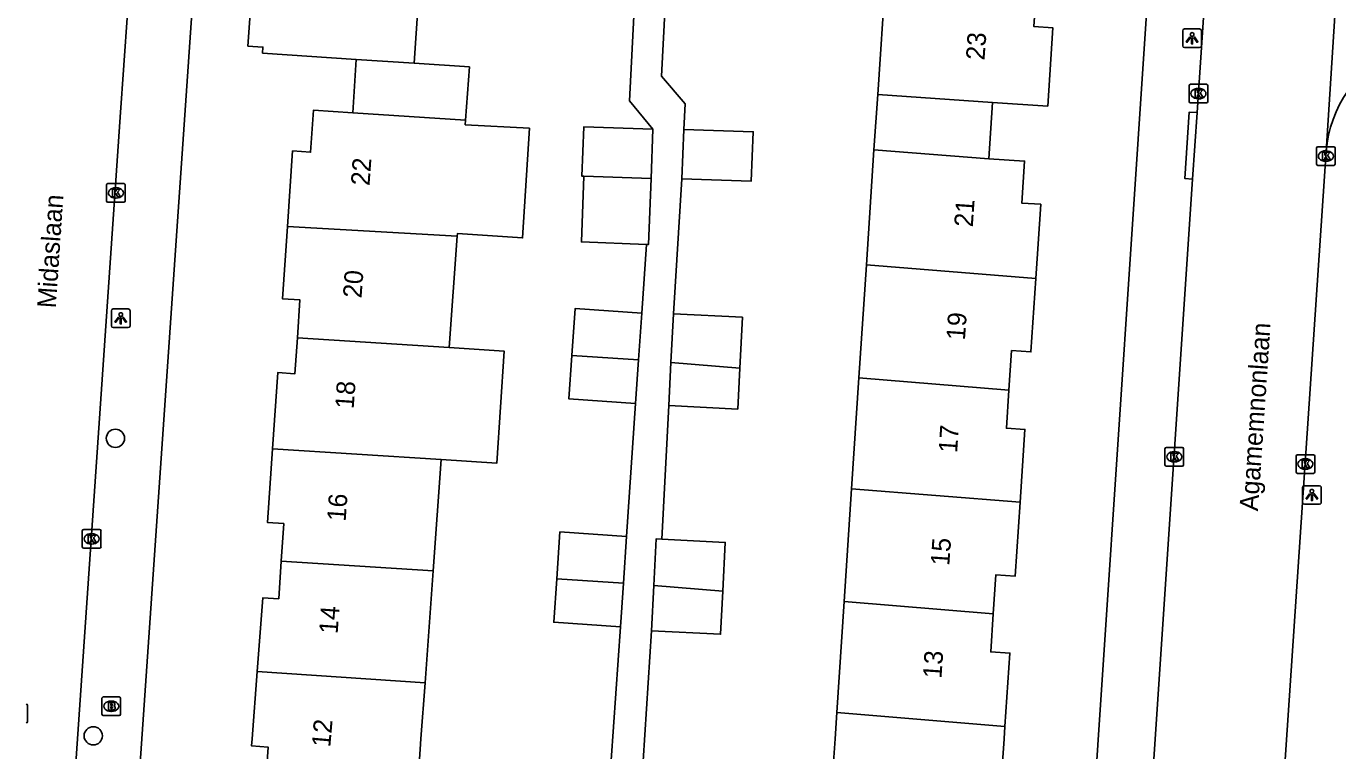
# Model space of a CAD drawing. Extents: x 161848 to 162726, y 385382 to 386521.
# Drawn here: x 162160.7 to 162231, y 385499.4 to 385538.2 of the extents above; entities that cross this region are included whole.
import ezdxf

# ---------------------------------------------------------------- set-up
doc = ezdxf.new("R2010")
doc.units = 0
for name, color, linetype in [('IMGEO_Boom', 7, 'Continuous'), ('IMGEO_Brandkraan', 7, 'Continuous'), ('IMGEO_Kolk', 7, 'Continuous'), ('IMGEO_Lichtpunt', 7, 'Continuous'), ('IMGEO_Openbare_ruimte_label', 7, 'Continuous'), ('IMGEO_Pand', 7, 'Continuous'), ('IMGEO_Pand_nummerreeks', 7, 'Continuous'), ('IMGEO_Rijbaan_lokaal_open', 7, 'Continuous'), ('IMGEO_Rioolput', 7, 'Continuous'), ('IMGEO_Voetpad_open', 7, 'Continuous')]:
    doc.layers.add(name, color=color, linetype=linetype)

msp = doc.modelspace()

# ---------------------------------------------------------------- linework, layer by layer
at = {"layer": 'IMGEO_Boom'}
for centre in [(162165.493, 385516.112), (162164.305, 385500.163)]:
    msp.add_circle(centre, 0.489, dxfattribs=at)
at = {"layer": 'IMGEO_Brandkraan'}
for p, q in [((162164.77, 385501.322), (162164.77, 385502.174)), ((162164.845, 385502.248), (162165.697, 385502.248)), ((162165.258, 385502.028), (162165.283, 385502.028)), ((162165.771, 385502.174), (162165.771, 385501.322)), ((162165.281, 385501.468), (162165.256, 385501.468)), ((162165.697, 385501.248), (162164.845, 385501.248))]:
    msp.add_line(p, q, dxfattribs=at)
for points in [[(162164.77, 385501.322), (162164.77, 385502.174)], [(162164.845, 385502.248), (162165.697, 385502.248)], [(162165.771, 385502.174), (162165.771, 385501.322)], [(162165.118, 385501.948), (162165.118, 385501.548), (162165.331, 385501.548)], [(162165.349, 385501.948), (162165.118, 385501.948)], [(162165.297, 385501.867), (162165.243, 385501.867), (162165.243, 385501.791)], [(162165.243, 385501.791), (162165.296, 385501.791)], [(162165.305, 385501.715), (162165.243, 385501.715), (162165.243, 385501.634)], [(162165.243, 385501.634), (162165.305, 385501.634)], [(162165.697, 385501.248), (162164.845, 385501.248)]]:
    msp.add_lwpolyline(points, dxfattribs=at)
for centre, radius, start, end in [((162164.847, 385502.172), 0.0765, 91.55205, 178.44795), ((162164.847, 385502.172), 0.0765, 91.55205, 178.44795), ((162165.695, 385502.172), 0.0765, 1.55205, 88.44795), ((162165.695, 385502.172), 0.0765, 1.55205, 88.44795), ((162164.847, 385501.324), 0.0765, 181.55205, 268.44795), ((162164.847, 385501.324), 0.0765, 181.55205, 268.44795), ((162165.298, 385501.829), 0.0379, 267.82845, 90.93552), ((162165.306, 385501.674), 0.0404, 269.87594, 90.50774), ((162165.337, 385501.799), 0.251, 268.66757, 293.53466), ((162165.353, 385501.803), 0.145, 59.4692, 91.53667), ((162165.378, 385501.85), 0.0922, 285.51372, 58.15012), ((162165.383, 385501.658), 0.105, 301.31148, 78.98903), ((162165.695, 385501.324), 0.0765, 271.55205, 358.44795), ((162165.695, 385501.324), 0.0765, 271.55205, 358.44795)]:
    msp.add_arc(centre, radius, start, end, dxfattribs=at)
for centre, major_axis, ratio, start_param, end_param in [((162165.257, 385501.748), (-0.387, 0.002), 0.722429, 4.712389, 7.853982), ((162165.282, 385501.748), (-0.39, 0.002), 0.717154, 1.570796, 4.712389)]:
    msp.add_ellipse(centre, major_axis=major_axis, ratio=ratio, start_param=start_param, end_param=end_param, dxfattribs=at)
at = {"layer": 'IMGEO_Kolk'}
for p, q in [((162223.096, 385535.09), (162223.948, 385535.09)), ((162223.021, 385534.164), (162223.021, 385535.016)), ((162223.509, 385534.87), (162223.534, 385534.87)), ((162224.022, 385535.016), (162224.022, 385534.164)), ((162223.948, 385534.09), (162223.096, 385534.09)), ((162223.532, 385534.31), (162223.507, 385534.31)), ((162229.846, 385530.818), (162229.846, 385531.67)), ((162229.921, 385531.744), (162230.773, 385531.744)), ((162230.334, 385531.524), (162230.359, 385531.524)), ((162230.847, 385531.67), (162230.847, 385530.818)), ((162230.357, 385530.964), (162230.332, 385530.964)), ((162230.773, 385530.744), (162229.921, 385530.744)), ((162165.018, 385528.84), (162165.018, 385529.692)), ((162165.093, 385529.766), (162165.945, 385529.766)), ((162165.506, 385529.546), (162165.531, 385529.546)), ((162166.019, 385529.692), (162166.019, 385528.84)), ((162165.945, 385528.766), (162165.093, 385528.766)), ((162165.529, 385528.986), (162165.504, 385528.986)), ((162221.727, 385514.698), (162221.727, 385515.55)), ((162221.802, 385515.624), (162222.654, 385515.624)), ((162222.215, 385515.404), (162222.24, 385515.404)), ((162222.728, 385515.55), (162222.728, 385514.698)), ((162222.238, 385514.844), (162222.213, 385514.844)), ((162228.752, 385514.308), (162228.752, 385515.16)), ((162228.827, 385515.234), (162229.679, 385515.234)), ((162229.24, 385515.014), (162229.265, 385515.014)), ((162229.753, 385515.16), (162229.753, 385514.308)), ((162222.654, 385514.624), (162221.802, 385514.624)), ((162229.679, 385514.234), (162228.827, 385514.234)), ((162229.263, 385514.454), (162229.238, 385514.454)), ((162163.719, 385510.296), (162163.719, 385511.148)), ((162163.794, 385511.222), (162164.646, 385511.222)), ((162164.72, 385511.148), (162164.72, 385510.296)), ((162164.23, 385510.442), (162164.205, 385510.442)), ((162164.207, 385511.002), (162164.232, 385511.002)), ((162164.646, 385510.222), (162163.794, 385510.222))]:
    msp.add_line(p, q, dxfattribs=at)
for points in [[(162223.096, 385535.09), (162223.948, 385535.09)], [(162223.021, 385534.164), (162223.021, 385535.016)], [(162223.342, 385534.79), (162223.465, 385534.79), (162223.465, 385534.639), (162223.595, 385534.79), (162223.759, 385534.79), (162223.613, 385534.639), (162223.766, 385534.39), (162223.614, 385534.39), (162223.529, 385534.554), (162223.465, 385534.487), (162223.465, 385534.39), (162223.342, 385534.39), (162223.342, 385534.79)], [(162224.022, 385535.016), (162224.022, 385534.164)], [(162223.948, 385534.09), (162223.096, 385534.09)], [(162229.846, 385530.818), (162229.846, 385531.67)], [(162229.921, 385531.744), (162230.773, 385531.744)], [(162230.847, 385531.67), (162230.847, 385530.818)], [(162230.167, 385531.444), (162230.29, 385531.444), (162230.29, 385531.293), (162230.42, 385531.444), (162230.584, 385531.444), (162230.438, 385531.293), (162230.591, 385531.044), (162230.439, 385531.044), (162230.354, 385531.208), (162230.29, 385531.141), (162230.29, 385531.044), (162230.167, 385531.044), (162230.167, 385531.444)], [(162230.773, 385530.744), (162229.921, 385530.744)], [(162165.018, 385528.84), (162165.018, 385529.692)], [(162165.093, 385529.766), (162165.945, 385529.766)], [(162165.339, 385529.466), (162165.462, 385529.466), (162165.462, 385529.315), (162165.592, 385529.466), (162165.756, 385529.466), (162165.61, 385529.315), (162165.763, 385529.066), (162165.611, 385529.066), (162165.526, 385529.23), (162165.462, 385529.163), (162165.462, 385529.066), (162165.339, 385529.066), (162165.339, 385529.466)], [(162166.019, 385529.692), (162166.019, 385528.84)], [(162165.945, 385528.766), (162165.093, 385528.766)], [(162221.727, 385514.698), (162221.727, 385515.55)], [(162221.802, 385515.624), (162222.654, 385515.624)], [(162222.728, 385515.55), (162222.728, 385514.698)], [(162222.048, 385515.324), (162222.171, 385515.324), (162222.171, 385515.173), (162222.301, 385515.324), (162222.465, 385515.324), (162222.319, 385515.173), (162222.472, 385514.924), (162222.32, 385514.924), (162222.235, 385515.088), (162222.171, 385515.021), (162222.171, 385514.924), (162222.048, 385514.924), (162222.048, 385515.324)], [(162228.752, 385514.308), (162228.752, 385515.16)], [(162228.827, 385515.234), (162229.679, 385515.234)], [(162229.073, 385514.934), (162229.196, 385514.934), (162229.196, 385514.783), (162229.326, 385514.934), (162229.49, 385514.934), (162229.344, 385514.783), (162229.497, 385514.534), (162229.345, 385514.534), (162229.26, 385514.698), (162229.196, 385514.631), (162229.196, 385514.534), (162229.073, 385514.534), (162229.073, 385514.934)], [(162229.753, 385515.16), (162229.753, 385514.308)], [(162222.654, 385514.624), (162221.802, 385514.624)], [(162229.679, 385514.234), (162228.827, 385514.234)], [(162163.719, 385510.296), (162163.719, 385511.148)], [(162163.794, 385511.222), (162164.646, 385511.222)], [(162164.72, 385511.148), (162164.72, 385510.296)], [(162164.04, 385510.922), (162164.163, 385510.922), (162164.163, 385510.771), (162164.293, 385510.922), (162164.457, 385510.922), (162164.311, 385510.771), (162164.464, 385510.522), (162164.312, 385510.522), (162164.227, 385510.686), (162164.163, 385510.619), (162164.163, 385510.522), (162164.04, 385510.522), (162164.04, 385510.922)], [(162164.646, 385510.222), (162163.794, 385510.222)]]:
    msp.add_lwpolyline(points, dxfattribs=at)
for centre, start, end in [((162223.098, 385535.014), 91.55205, 178.44795), ((162223.098, 385535.014), 91.55205, 178.44795), ((162223.946, 385535.014), 1.55205, 88.44795), ((162223.946, 385535.014), 1.55205, 88.44795), ((162223.098, 385534.166), 181.55205, 268.44795), ((162223.098, 385534.166), 181.55205, 268.44795), ((162223.946, 385534.166), 271.55205, 358.44795), ((162223.946, 385534.166), 271.55205, 358.44795), ((162229.923, 385531.668), 91.55205, 178.44795), ((162229.923, 385531.668), 91.55205, 178.44795), ((162230.771, 385531.668), 1.55205, 88.44795), ((162230.771, 385531.668), 1.55205, 88.44795), ((162229.923, 385530.82), 181.55205, 268.44795), ((162229.923, 385530.82), 181.55205, 268.44795), ((162230.771, 385530.82), 271.55205, 358.44795), ((162230.771, 385530.82), 271.55205, 358.44795), ((162165.095, 385529.69), 91.55205, 178.44795), ((162165.095, 385529.69), 91.55205, 178.44795), ((162165.943, 385529.69), 1.55205, 88.44795), ((162165.943, 385529.69), 1.55205, 88.44795), ((162165.095, 385528.842), 181.55205, 268.44795), ((162165.095, 385528.842), 181.55205, 268.44795), ((162165.943, 385528.842), 271.55205, 358.44795), ((162165.943, 385528.842), 271.55205, 358.44795), ((162221.804, 385515.548), 91.55205, 178.44795), ((162221.804, 385515.548), 91.55205, 178.44795), ((162222.652, 385515.548), 1.55205, 88.44795), ((162222.652, 385515.548), 1.55205, 88.44795), ((162221.804, 385514.7), 181.55205, 268.44795), ((162221.804, 385514.7), 181.55205, 268.44795), ((162222.652, 385514.7), 271.55205, 358.44795), ((162222.652, 385514.7), 271.55205, 358.44795), ((162228.829, 385515.158), 91.55205, 178.44795), ((162228.829, 385515.158), 91.55205, 178.44795), ((162229.677, 385515.158), 1.55205, 88.44795), ((162229.677, 385515.158), 1.55205, 88.44795), ((162228.829, 385514.31), 181.55205, 268.44795), ((162228.829, 385514.31), 181.55205, 268.44795), ((162229.677, 385514.31), 271.55205, 358.44795), ((162229.677, 385514.31), 271.55205, 358.44795), ((162163.796, 385511.146), 91.55205, 178.44795), ((162163.796, 385511.146), 91.55205, 178.44795), ((162164.644, 385511.146), 1.55205, 88.44795), ((162164.644, 385511.146), 1.55205, 88.44795), ((162163.796, 385510.298), 181.55205, 268.44795), ((162163.796, 385510.298), 181.55205, 268.44795), ((162164.644, 385510.298), 271.55205, 358.44795), ((162164.644, 385510.298), 271.55205, 358.44795)]:
    msp.add_arc(centre, 0.0765, start, end, dxfattribs=at)
for centre, major_axis, ratio, start_param, end_param in [((162223.508, 385534.59), (-0.387, 0.002), 0.722429, 4.712389, 7.853982), ((162223.533, 385534.59), (-0.39, 0.002), 0.717154, 1.570796, 4.712389), ((162230.333, 385531.244), (-0.387, 0.002), 0.722429, 4.712389, 7.853982), ((162230.358, 385531.244), (-0.39, 0.002), 0.717154, 1.570796, 4.712389), ((162165.505, 385529.266), (-0.387, 0.002), 0.722429, 4.712389, 7.853982), ((162165.53, 385529.266), (-0.39, 0.002), 0.717154, 1.570796, 4.712389), ((162222.214, 385515.124), (-0.387, 0.002), 0.722429, 4.712389, 7.853982), ((162222.239, 385515.124), (-0.39, 0.002), 0.717154, 1.570796, 4.712389), ((162229.239, 385514.734), (-0.387, 0.002), 0.722429, 4.712389, 7.853982), ((162229.264, 385514.734), (-0.39, 0.002), 0.717154, 1.570796, 4.712389), ((162164.206, 385510.722), (-0.387, 0.002), 0.722429, 4.712389, 7.853982), ((162164.231, 385510.722), (-0.39, 0.002), 0.717154, 1.570796, 4.712389)]:
    msp.add_ellipse(centre, major_axis=major_axis, ratio=ratio, start_param=start_param, end_param=end_param, dxfattribs=at)
at = {"layer": 'IMGEO_Lichtpunt'}
for p, q in [((162222.68, 385537.963), (162222.68, 385537.156)), ((162222.68, 385537.963), (162222.68, 385537.156)), ((162223.582, 385538.058), (162222.774, 385538.058)), ((162223.582, 385538.058), (162222.774, 385538.058)), ((162223.676, 385537.156), (162223.676, 385537.963)), ((162223.676, 385537.156), (162223.676, 385537.963)), ((162222.774, 385537.062), (162223.582, 385537.062)), ((162222.774, 385537.062), (162223.582, 385537.062)), ((162165.28, 385522.95), (162165.28, 385522.143)), ((162165.28, 385522.95), (162165.28, 385522.143)), ((162166.182, 385523.045), (162165.374, 385523.045)), ((162166.182, 385523.045), (162165.374, 385523.045)), ((162166.276, 385522.143), (162166.276, 385522.95)), ((162166.276, 385522.143), (162166.276, 385522.95)), ((162165.374, 385522.049), (162166.182, 385522.049)), ((162165.374, 385522.049), (162166.182, 385522.049)), ((162229.102, 385513.476), (162229.102, 385512.669)), ((162229.102, 385513.476), (162229.102, 385512.669)), ((162230.004, 385513.571), (162229.196, 385513.571)), ((162230.004, 385513.571), (162229.196, 385513.571)), ((162230.098, 385512.669), (162230.098, 385513.476)), ((162230.098, 385512.669), (162230.098, 385513.476)), ((162229.196, 385512.575), (162230.004, 385512.575)), ((162229.196, 385512.575), (162230.004, 385512.575))]:
    msp.add_line(p, q, dxfattribs=at)
for points in [[(162223.054, 385537.627), (162223.093, 385537.599), (162222.905, 385537.337), (162222.867, 385537.364), (162223.054, 385537.627)], [(162223.156, 385537.579), (162223.203, 385537.579), (162223.203, 385537.257), (162223.156, 385537.257), (162223.156, 385537.579)], [(162223.266, 385537.599), (162223.304, 385537.626), (162223.491, 385537.364), (162223.452, 385537.336), (162223.266, 385537.599)], [(162165.654, 385522.614), (162165.693, 385522.586), (162165.505, 385522.324), (162165.467, 385522.351), (162165.654, 385522.614)], [(162165.756, 385522.566), (162165.803, 385522.566), (162165.803, 385522.244), (162165.756, 385522.244), (162165.756, 385522.566)], [(162165.866, 385522.586), (162165.904, 385522.613), (162166.091, 385522.351), (162166.052, 385522.323), (162165.866, 385522.586)], [(162229.476, 385513.14), (162229.515, 385513.112), (162229.327, 385512.85), (162229.289, 385512.877), (162229.476, 385513.14)], [(162229.578, 385513.092), (162229.625, 385513.092), (162229.625, 385512.77), (162229.578, 385512.77), (162229.578, 385513.092)], [(162229.688, 385513.112), (162229.726, 385513.139), (162229.913, 385512.877), (162229.874, 385512.849), (162229.688, 385513.112)]]:
    msp.add_lwpolyline(points, dxfattribs=at)
for centre in [(162223.179, 385537.761), (162165.779, 385522.748), (162229.601, 385513.274)]:
    msp.add_circle(centre, 0.0994, dxfattribs=at)
for centre, start, end in [((162222.774, 385537.963), 90, 180), ((162222.774, 385537.963), 90, 180), ((162223.582, 385537.963), 0, 90), ((162223.582, 385537.963), 0, 90), ((162222.774, 385537.156), 180, 270), ((162222.774, 385537.156), 180, 270), ((162223.582, 385537.156), 270, 0), ((162223.582, 385537.156), 270, 360), ((162165.374, 385522.95), 90, 180), ((162165.374, 385522.95), 90, 180), ((162166.182, 385522.95), 0, 90), ((162166.182, 385522.95), 0, 90), ((162165.374, 385522.143), 180, 270), ((162165.374, 385522.143), 180, 270), ((162166.182, 385522.143), 270, 0), ((162166.182, 385522.143), 270, 360), ((162229.196, 385513.476), 90, 180), ((162229.196, 385513.476), 90, 180), ((162230.004, 385513.476), 0, 90), ((162230.004, 385513.476), 0, 90), ((162229.196, 385512.669), 180, 270), ((162229.196, 385512.669), 180, 270), ((162230.004, 385512.669), 270, 0), ((162230.004, 385512.669), 270, 360)]:
    msp.add_arc(centre, 0.0946, start, end, dxfattribs=at)
at = {"layer": 'IMGEO_Pand'}
for points in [[(162178.4, 385536.42), (162173.375, 385536.763), (162173.397, 385537.084), (162172.594, 385537.139), (162172.849, 385540.88), (162173.652, 385540.825), (162173.793, 385542.892)], [(162181.916, 385542.371), (162181.497, 385536.226)], [(162206.335, 385534.539), (162206.748, 385540.784)], [(162214.845, 385540.226), (162214.709, 385538.18), (162215.727, 385538.112), (162215.45, 385533.918), (162212.489, 385534.113)], [(162178.206, 385533.562), (162178.4, 385536.42)], [(162178.4, 385536.42), (162181.497, 385536.226)], [(162181.497, 385536.226), (162184.457, 385536.024), (162184.251, 385533.167)], [(162206.135, 385531.571), (162206.335, 385534.539)], [(162206.335, 385534.539), (162212.489, 385534.113)], [(162178.206, 385533.562), (162176.107, 385533.705), (162175.953, 385531.449), (162174.983, 385531.515), (162174.707, 385527.47)], [(162212.489, 385534.113), (162212.29, 385531.1)], [(162184.251, 385533.167), (162178.206, 385533.562)], [(162184.251, 385533.167), (162184.233, 385532.921), (162187.677, 385532.734), (162187.305, 385526.856), (162183.813, 385527.085), (162183.804, 385526.953)], [(162194.296, 385532.69), (162190.584, 385532.808), (162190.48, 385530.166), (162190.597, 385530.162)], [(162194.191, 385530.047), (162194.296, 385532.69)], [(162195.953, 385532.661), (162199.664, 385532.543), (162199.559, 385529.9), (162195.848, 385530.019)], [(162195.848, 385530.019), (162195.953, 385532.661)], [(162205.733, 385525.42), (162206.135, 385531.571)], [(162212.29, 385531.1), (162206.135, 385531.571)], [(162212.29, 385531.1), (162214.201, 385530.974), (162214.053, 385528.726), (162215.07, 385528.658), (162214.808, 385524.684)], [(162190.597, 385530.162), (162190.457, 385526.639), (162193.947, 385526.501)], [(162194.191, 385530.047), (162190.597, 385530.162)], [(162193.947, 385526.501), (162194.05, 385526.497), (162194.191, 385530.047)], [(162174.707, 385527.47), (162174.443, 385523.592), (162175.382, 385523.528), (162175.244, 385521.495)], [(162183.804, 385526.953), (162174.707, 385527.47)], [(162183.374, 385520.975), (162183.804, 385526.953)], [(162205.332, 385519.35), (162205.733, 385525.42)], [(162214.808, 385524.684), (162205.733, 385525.42)], [(162214.808, 385524.684), (162214.548, 385520.744), (162213.506, 385520.813), (162213.365, 385518.685)], [(162189.952, 385520.554), (162190.122, 385523.064), (162193.693, 385522.822)], [(162193.693, 385522.822), (162193.524, 385520.326)], [(162195.258, 385520.184), (162195.391, 385522.792)], [(162195.391, 385522.792), (162199.085, 385522.603), (162198.946, 385519.879)], [(162175.244, 385521.495), (162175.113, 385519.575), (162174.186, 385519.638), (162173.907, 385515.544)], [(162183.374, 385520.975), (162175.244, 385521.495)], [(162182.943, 385514.976), (162185.935, 385514.788), (162186.318, 385520.787), (162183.374, 385520.975)], [(162193.366, 385517.98), (162189.795, 385518.222), (162189.952, 385520.554)], [(162189.952, 385520.554), (162193.524, 385520.326)], [(162193.524, 385520.326), (162193.366, 385517.98)], [(162195.14, 385517.864), (162195.258, 385520.184)], [(162198.946, 385519.879), (162198.834, 385517.675), (162195.14, 385517.864)], [(162195.258, 385520.184), (162198.946, 385519.879)], [(162204.939, 385513.397), (162205.332, 385519.35)], [(162205.332, 385519.35), (162213.365, 385518.685)], [(162213.365, 385518.685), (162213.231, 385516.652), (162214.221, 385516.586), (162213.963, 385512.681)], [(162173.907, 385515.544), (162173.638, 385511.602), (162174.516, 385511.542), (162174.379, 385509.525)], [(162173.907, 385515.544), (162182.943, 385514.976)], [(162182.513, 385509.005), (162182.943, 385514.976)], [(162204.541, 385507.369), (162204.939, 385513.397)], [(162204.939, 385513.397), (162213.963, 385512.681)], [(162213.963, 385512.681), (162213.702, 385508.728), (162212.667, 385508.797), (162212.529, 385506.701)], [(162189.136, 385508.582), (162189.305, 385511.094), (162192.876, 385510.852)], [(162192.876, 385510.852), (162192.708, 385508.353)], [(162194.344, 385508.222), (162194.471, 385510.724), (162194.774, 385510.709)], [(162194.774, 385510.709), (162198.166, 385510.535), (162198.032, 385507.913)], [(162174.379, 385509.525), (162174.242, 385507.508), (162173.396, 385507.566), (162173.095, 385503.617)], [(162182.513, 385509.005), (162174.379, 385509.525)], [(162182.081, 385503.007), (162182.513, 385509.005)], [(162192.549, 385506.01), (162188.978, 385506.252), (162189.136, 385508.582)], [(162192.708, 385508.353), (162189.136, 385508.582)], [(162192.708, 385508.353), (162192.549, 385506.01)], [(162194.22, 385505.796), (162194.344, 385508.222)], [(162198.032, 385507.913), (162197.914, 385505.607), (162194.22, 385505.796)], [(162194.344, 385508.222), (162198.032, 385507.913)], [(162204.148, 385501.418), (162204.541, 385507.369)], [(162204.541, 385507.369), (162212.529, 385506.701)], [(162212.529, 385506.701), (162212.394, 385504.664), (162213.416, 385504.596), (162213.152, 385500.665)], [(162173.095, 385503.617), (162172.819, 385500), (162172.79, 385499.62), (162173.673, 385499.559), (162173.532, 385497.525)], [(162182.081, 385503.007), (162173.095, 385503.617)], [(162181.665, 385496.979), (162181.865, 385500), (162182.081, 385503.007)], [(162203.737, 385495.507), (162204.054, 385500), (162204.148, 385501.418)], [(162213.152, 385500.665), (162204.148, 385501.418)], [(162213.152, 385500.665), (162213.107, 385500), (162212.888, 385496.736), (162211.828, 385496.796), (162211.725, 385494.976)]]:
    msp.add_lwpolyline(points, dxfattribs=at)
at = {"layer": 'IMGEO_Rijbaan_lokaal_open'}
for points in [[(162168.482, 385573.131), (162166.136, 385538.907), (162165.753, 385533.321), (162163.468, 385500), (162161.151, 385466.324)], [(162223.444, 385533.57), (162225.631, 385566.308)], [(162230.36, 385531.483), (162231.543, 385549.956)], [(162223.444, 385533.57), (162223.206, 385530.013)], [(162230.36, 385531.483), (162221.906, 385405.85), (162221.191, 385395.939)], [(162218.979, 385466.744), (162223.206, 385530.013)]]:
    msp.add_lwpolyline(points, dxfattribs=at)
msp.add_arc((162236.918, 385530.965), 6.578, 114.27767, 175.48037, dxfattribs=at)
at = {"layer": 'IMGEO_Rioolput'}
msp.add_line((162160.788, 385501.783), (162160.788, 385500.931), dxfattribs=at)
msp.add_lwpolyline([(162160.788, 385501.783), (162160.788, 385500.931)], dxfattribs=at)
for centre, start, end in [((162160.712, 385501.781), 1.55205, 88.44795), ((162160.712, 385501.781), 1.55205, 88.44795), ((162160.712, 385500.933), 271.55205, 358.44795), ((162160.712, 385500.933), 271.55205, 358.44795)]:
    msp.add_arc(centre, 0.0765, start, end, dxfattribs=at)
at = {"layer": 'IMGEO_Voetpad_open'}
for points in [[(162164.7, 385467.939), (162166.909, 385500), (162171.93, 385572.873)], [(162215.621, 385462.079), (162222.785, 385569.764)], [(162193.3, 385539.431), (162193.033, 385534.21), (162194.296, 385532.69)], [(162194.951, 385539.29), (162194.76, 385535.529), (162196.011, 385534.048), (162195.953, 385532.661)], [(162223.206, 385530.013), (162222.787, 385530.043), (162223.025, 385533.6), (162223.444, 385533.57)], [(162195.848, 385530.019), (162195.391, 385522.792)], [(162193.947, 385526.501), (162193.693, 385522.822)], [(162193.366, 385517.98), (162192.876, 385510.852)], [(162195.14, 385517.864), (162194.774, 385510.709)], [(162192.549, 385506.01), (162192.047, 385498.852)], [(162194.22, 385505.796), (162193.762, 385498.821)]]:
    msp.add_lwpolyline(points, dxfattribs=at)

# ---------------------------------------------------------------- texts
at = {"layer": 'IMGEO_Openbare_ruimte_label'}
for s, p in [('Midaslaan', (162162.298, 385523.068)), ('Agamemnonlaan', (162226.709, 385512.192))]:
    msp.add_text(s, height=1, rotation=86.15925, dxfattribs=at).set_placement(p)
at = {"layer": 'IMGEO_Pand_nummerreeks'}
for s, rotation, p in [('23', 86.01643, (162212.056, 385536.36)), ('22', 85.93221, (162179.105, 385529.63)), ('21', 86.03018, (162211.427, 385527.415)), ('20', 85.93216, (162178.677, 385523.606)), ('19', 86.03018, (162211.007, 385521.348)), ('18', 85.93221, (162178.255, 385517.667)), ('17', 86.03018, (162210.587, 385515.304)), ('16', 85.93216, (162177.826, 385511.634)), ('15', 86.03018, (162210.168, 385509.26)), ('14', 85.93216, (162177.397, 385505.604)), ('13', 86.03018, (162209.748, 385503.216)), ('12', 85.03008, (162177.002, 385499.527))]:
    msp.add_text(s, height=1, rotation=rotation, dxfattribs=at).set_placement(p)

doc.saveas('drawing.dxf')
